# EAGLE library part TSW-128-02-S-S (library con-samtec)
THROUGH-HOLE .025" SQ POST HEADER Source: Samtec TSW.pdf
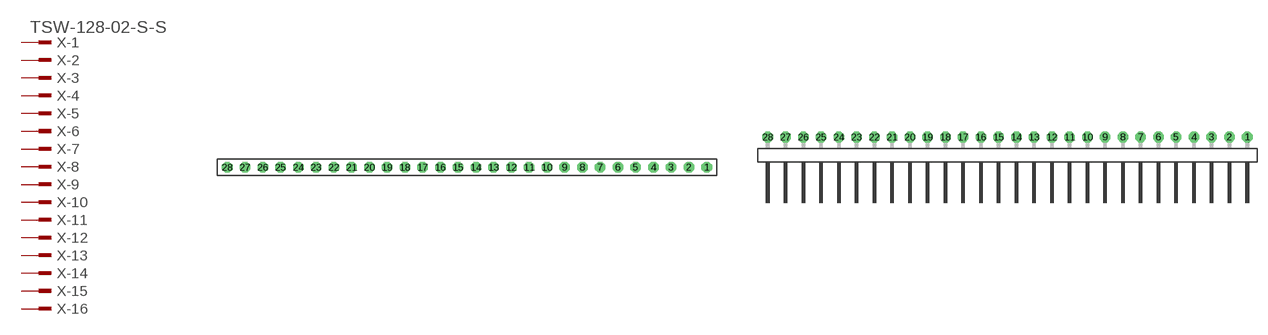
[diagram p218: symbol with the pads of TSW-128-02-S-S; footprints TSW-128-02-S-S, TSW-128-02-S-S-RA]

Designator prefix X; gates -1=MPINV -2=MPIN -3=MPIN -4=MPIN -5=MPIN -6=MPIN -7=MPIN -8=MPIN -9=MPIN -10=MPIN -11=MPIN -12=MPIN -13=MPIN -14=MPIN -15=MPIN -16=MPIN -17=MPIN -18=MPIN -19=MPIN -20=MPIN -21=MPIN -22=MPIN -23=MPIN -24=MPIN -25=MPIN -26=MPIN -27=MPIN -28=MPIN

## TSW-128-02-S-S (OC_FARNELL: unknown; OC_NEWARK: unknown)  [TSW-128-02-S-S]
1  -1:1  pas
2  -2:1  pas
3  -3:1  pas
4  -4:1  pas
5  -5:1  pas
6  -6:1  pas
7  -7:1  pas
8  -8:1  pas
9  -9:1  pas
10  -10:1  pas
11  -11:1  pas
12  -12:1  pas
13  -13:1  pas
14  -14:1  pas
15  -15:1  pas
16  -16:1  pas
17  -17:1  pas
18  -18:1  pas
19  -19:1  pas
20  -20:1  pas
21  -21:1  pas
22  -22:1  pas
23  -23:1  pas
24  -24:1  pas
25  -25:1  pas
26  -26:1  pas
27  -27:1  pas
28  -28:1  pas

## TSW-128-02-S-S-RA (OC_FARNELL: unknown; OC_NEWARK: unknown)  [TSW-128-02-S-S-RA]
Pads as for TSW-128-02-S-S

## Footprint TSW-128-02-S-S (pad centres in mm)
THROUGH-HOLE .025" SQ POST HEADER Source: Samtec TSW.pdf
drill 1 pad 1.5 octagon: 1 34.29,0; 2 31.75,0; 3 29.21,0; 4 26.67,0; 5 24.13,0; 6 21.59,0; 7 19.05,0; 8 16.51,0; 9 13.97,0; 10 11.43,0; 11 8.89,0; 12 6.35,0; 13 3.81,0; 14 1.27,0; 15 -1.27,0; 16 -3.81,0; 17 -6.35,0; 18 -8.89,0; 19 -11.43,0; 20 -13.97,0; 21 -16.51,0; 22 -19.05,0; 23 -21.59,0; 24 -24.13,0; 25 -26.67,0; 26 -29.21,0; 27 -31.75,0; 28 -34.29,0

## Footprint TSW-128-02-S-S-RA (pad centres in mm)
THROUGH-HOLE .025" SQ POST HEADER Source: Samtec TSW.pdf
drill 1 pad 1.5 octagon: 1 34.29,1.524; 2 31.75,1.524; 3 29.21,1.524; 4 26.67,1.524; 5 24.13,1.524; 6 21.59,1.524; 7 19.05,1.524; 8 16.51,1.524; 9 13.97,1.524; 10 11.43,1.524; 11 8.89,1.524; 12 6.35,1.524; 13 3.81,1.524; 14 1.27,1.524; 15 -1.27,1.524; 16 -3.81,1.524; 17 -6.35,1.524; 18 -8.89,1.524; 19 -11.43,1.524; 20 -13.97,1.524; 21 -16.51,1.524; 22 -19.05,1.524; 23 -21.59,1.524; 24 -24.13,1.524; 25 -26.67,1.524; 26 -29.21,1.524; 27 -31.75,1.524; 28 -34.29,1.524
